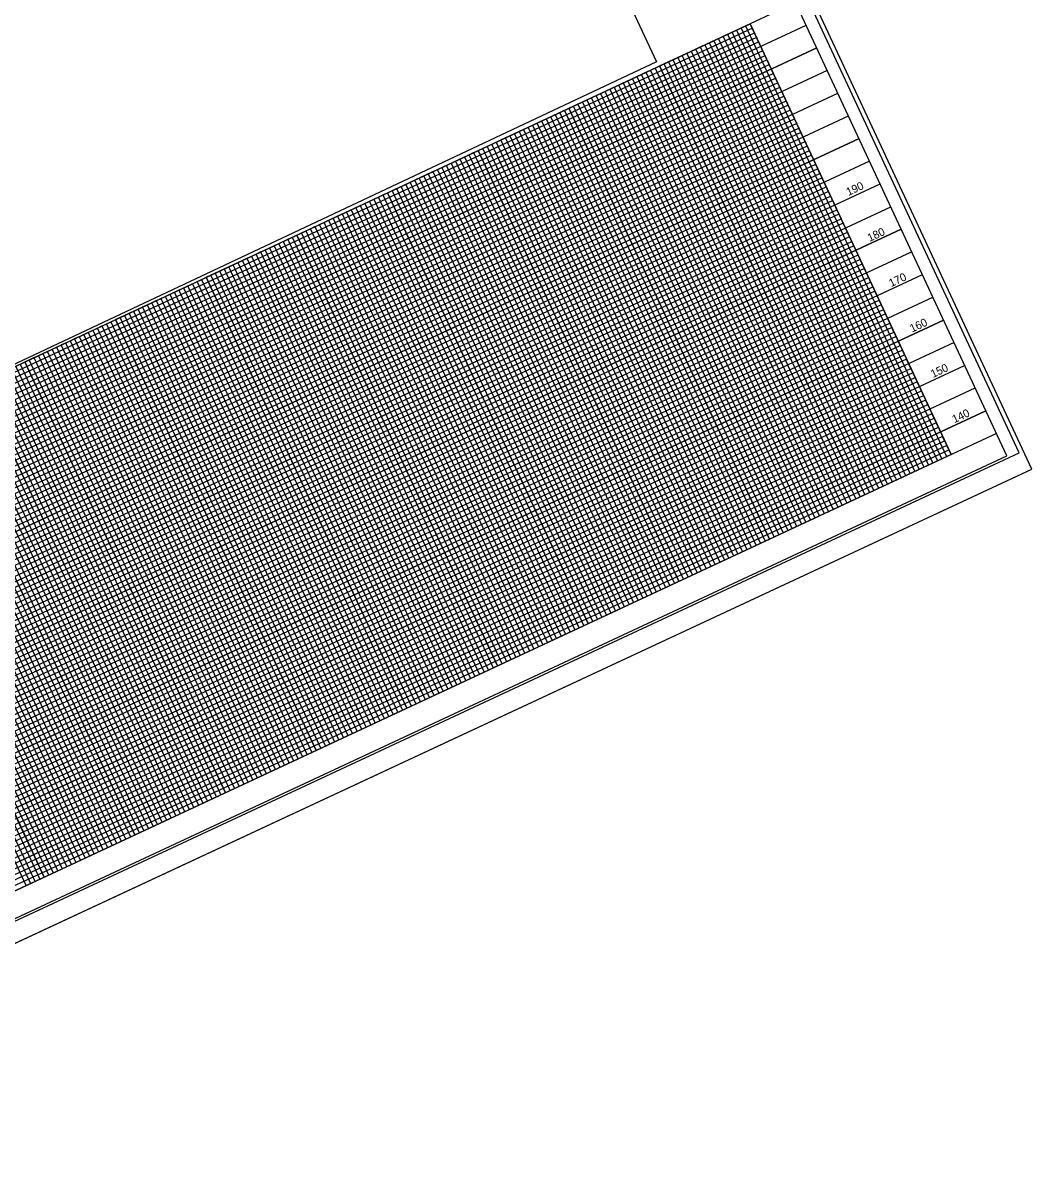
# Model space of a CAD drawing. Extents: x 2321825 to 2323872, y 921700 to 923436.
# Drawn here: x 2322864 to 2323872, y 921700 to 922857 of the extents above; entities that cross this region are included whole.
import ezdxf

# ---------------------------------------------------------------- set-up
doc = ezdxf.new("R2010")
doc.units = 0
for name, color, linetype in [('Default', 7, 'Continuous'), ('Sheet Cutting Line CELL', 7, 'Continuous'), ('Sheet DOT Grid CELL', 7, 'Continuous'), ('Sheet Layout Plan Border', 7, 'Continuous'), ('Sheet Layout Profile Border Port 2', 7, 'Continuous'), ('Sheet Plan And Profile CELL', 7, 'Continuous'), ('Sheet Plot Border Inside CELL', 7, 'Continuous'), ('Sheet Plot Border Outside CELL', 7, 'Continuous'), ('Sheet Profile Grid Major CELL', 7, 'Continuous'), ('Sheet Profile Grid Middle CELL', 7, 'Continuous'), ('Sheet Profile Grid Minor CELL', 7, 'Continuous')]:
    doc.layers.add(name, color=color, linetype=linetype)

msp = doc.modelspace()

# ---------------------------------------------------------------- linework, layer by layer
at = {"layer": 'Sheet Cutting Line CELL'}
msp.add_line((2322346.1, 921699.6), (2323872, 922410.9), dxfattribs=at)
at = {"layer": 'Sheet DOT Grid CELL'}
for p, q in [((2322276.2, 922243.5), (2323635.8, 922877.3)), ((2323590.5, 922856.1), (2323791.2, 922425.6)), ((2322297.4, 922198.2), (2323656.9, 922831.9)), ((2323545.2, 922835), (2323745.8, 922404.5)), ((2323499.8, 922813.9), (2323700.5, 922383.4)), ((2322318.5, 922152.9), (2323678, 922786.6)), ((2323454.5, 922792.8), (2323655.2, 922362.2)), ((2323409.2, 922771.6), (2323609.9, 922341.1)), ((2323363.9, 922750.5), (2323564.6, 922320)), ((2322339.6, 922107.6), (2323699.2, 922741.3)), ((2323318.6, 922729.4), (2323519.2, 922298.9)), ((2323273.3, 922708.3), (2323473.9, 922277.7)), ((2322360.7, 922062.3), (2323720.3, 922696)), ((2323227.9, 922687.2), (2323428.6, 922256.6)), ((2323182.6, 922666), (2323383.3, 922235.5)), ((2322381.9, 922017), (2323741.4, 922650.7)), ((2323137.3, 922644.9), (2323338, 922214.4)), ((2323092, 922623.8), (2323292.7, 922193.3)), ((2322403, 921971.6), (2323762.5, 922605.4)), ((2323046.7, 922602.7), (2323247.3, 922172.1)), ((2323001.3, 922581.5), (2323202, 922151)), ((2322424.1, 921926.3), (2323783.7, 922560)), ((2322956, 922560.4), (2323156.7, 922129.9)), ((2322910.7, 922539.3), (2323111.4, 922108.8)), ((2322865.4, 922518.2), (2323066.1, 922087.6)), ((2322445.2, 921881), (2323804.8, 922514.7)), ((2322820.1, 922497), (2323020.7, 922066.5)), ((2322774.7, 922475.9), (2322975.4, 922045.4)), ((2322466.4, 921835.7), (2323825.9, 922469.4)), ((2322729.4, 922454.8), (2322930.1, 922024.3)), ((2322684.1, 922433.7), (2322884.8, 922003.1))]:
    msp.add_line(p, q, dxfattribs=at)
at = {"layer": 'Sheet Layout Plan Border'}
msp.add_lwpolyline([(2323496.8, 922818), (2322321.6, 922264.7), (2322282.6, 922345.7), (2322138.6, 922653.9), (2322100.4, 922737.9), (2323278.1, 923286)], close=True, dxfattribs=at)
at = {"layer": 'Sheet Layout Profile Border Port 2'}
msp.add_lwpolyline([(2322321.6, 922264.7), (2323590.5, 922856.1), (2323791.2, 922425.6), (2322522.2, 921834.1)], close=True, dxfattribs=at)
at = {"layer": 'Sheet Plan And Profile CELL'}
msp.add_line((2323836.5, 922446.7), (2322476.9, 921813), dxfattribs=at)
msp.add_lwpolyline([(2323403.4, 923375.8), (2322043.9, 922742.1), (2322487.5, 921790.4), (2323847, 922424.1)], close=True, dxfattribs=at)
at = {"layer": 'Sheet Plot Border Inside CELL'}
msp.add_lwpolyline([(2322349.4, 921723.2), (2323859.4, 922427.1), (2323413.7, 923383.3), (2321903.7, 922679.5)], close=True, dxfattribs=at)
at = {"layer": 'Sheet Plot Border Outside CELL'}
msp.add_lwpolyline([(2322346.1, 921699.6), (2323872, 922410.9), (2323409.3, 923403.3), (2321883.5, 922692.1)], close=True, dxfattribs=at)
at = {"layer": 'Sheet Profile Grid Major CELL'}
for points in [[(2322276.2, 922243.5), (2323635.8, 922877.3)], [(2323791.2, 922425.6), (2323590.5, 922856.1)], [(2323656.9, 922831.9), (2322297.4, 922198.2), (2322318.5, 922152.9), (2323678, 922786.6)], [(2323700.5, 922383.4), (2323499.8, 922813.9), (2323545.2, 922835), (2323745.8, 922404.5)], [(2323609.9, 922341.1), (2323409.2, 922771.6), (2323454.5, 922792.8), (2323655.2, 922362.2)], [(2323519.2, 922298.9), (2323318.6, 922729.4), (2323363.9, 922750.5), (2323564.6, 922320)], [(2323699.2, 922741.3), (2322339.6, 922107.6), (2322360.7, 922062.3), (2323720.3, 922696)], [(2323428.6, 922256.6), (2323227.9, 922687.2), (2323273.3, 922708.3), (2323473.9, 922277.7)], [(2323338, 922214.4), (2323137.3, 922644.9), (2323182.6, 922666), (2323383.3, 922235.5)], [(2323741.4, 922650.7), (2322381.9, 922017), (2322403, 921971.6), (2323762.5, 922605.4)], [(2323247.3, 922172.1), (2323046.7, 922602.7), (2323092, 922623.8), (2323292.7, 922193.3)], [(2323156.7, 922129.9), (2322956, 922560.4), (2323001.3, 922581.5), (2323202, 922151)], [(2323783.7, 922560), (2322424.1, 921926.3), (2322445.2, 921881), (2323804.8, 922514.7)], [(2323066.1, 922087.6), (2322865.4, 922518.2), (2322910.7, 922539.3), (2323111.4, 922108.8)], [(2322975.4, 922045.4), (2322774.7, 922475.9), (2322820.1, 922497), (2323020.7, 922066.5)], [(2323825.9, 922469.4), (2322466.4, 921835.7)], [(2322884.8, 922003.1), (2322684.1, 922433.7), (2322729.4, 922454.8), (2322930.1, 922024.3)]]:
    msp.add_lwpolyline(points, dxfattribs=at)
at = {"layer": 'Sheet Profile Grid Middle CELL'}
for p, q in [((2322286.8, 922220.9), (2323646.4, 922854.6)), ((2323667.5, 922809.3), (2322307.9, 922175.6)), ((2322329.1, 922130.3), (2323688.6, 922764)), ((2323709.7, 922718.7), (2322350.2, 922084.9)), ((2322371.3, 922039.6), (2323730.9, 922673.3)), ((2323752, 922628), (2322392.4, 921994.3)), ((2322413.5, 921949), (2323773.1, 922582.7)), ((2323794.2, 922537.4), (2322434.7, 921903.7)), ((2322455.8, 921858.3), (2323815.4, 922492.1))]:
    msp.add_line(p, q, dxfattribs=at)
for points in [[(2323723.2, 922393.9), (2323522.5, 922824.5), (2323567.8, 922845.6), (2323768.5, 922415.1)], [(2323632.5, 922351.7), (2323431.9, 922782.2), (2323477.2, 922803.3), (2323677.9, 922372.8)], [(2323541.9, 922309.4), (2323341.2, 922740), (2323386.5, 922761.1), (2323587.2, 922330.6)], [(2323451.3, 922267.2), (2323250.6, 922697.7), (2323295.9, 922718.8), (2323496.6, 922288.3)], [(2323360.6, 922224.9), (2323160, 922655.5), (2323205.3, 922676.6), (2323406, 922246.1)], [(2323270, 922182.7), (2323069.3, 922613.2), (2323114.6, 922634.3), (2323315.3, 922203.8)], [(2323179.4, 922140.4), (2322978.7, 922571), (2323024, 922592.1), (2323224.7, 922161.6)], [(2323088.7, 922098.2), (2322888, 922528.7), (2322933.4, 922549.8), (2323134, 922119.3)], [(2322998.1, 922055.9), (2322797.4, 922486.5), (2322842.7, 922507.6), (2323043.4, 922077.1)], [(2322907.4, 922013.7), (2322706.8, 922444.2), (2322752.1, 922465.3), (2322952.8, 922034.8)]]:
    msp.add_lwpolyline(points, dxfattribs=at)
at = {"layer": 'Sheet Profile Grid Minor CELL'}
for points in [[(2323782.1, 922421.4), (2323581.4, 922851.9), (2323585.9, 922854), (2323786.6, 922423.5)], [(2322325.8, 922255.6), (2323594.7, 922847.1), (2323592.6, 922851.6), (2322323.7, 922260.1)], [(2322330, 922246.5), (2323598.9, 922838), (2323596.8, 922842.5), (2322327.9, 922251.1)], [(2323759.4, 922410.8), (2323558.8, 922841.4), (2323563.3, 922843.5), (2323764, 922412.9)], [(2323773, 922417.2), (2323572.4, 922847.7), (2323576.9, 922849.8), (2323777.6, 922419.3)], [(2323736.8, 922400.3), (2323536.1, 922830.8), (2323540.6, 922832.9), (2323741.3, 922402.4)], [(2323750.4, 922406.6), (2323549.7, 922837.1), (2323554.2, 922839.2), (2323754.9, 922408.7)], [(2322336.3, 922232.9), (2323605.3, 922824.4), (2323603.2, 922829), (2322334.2, 922237.5)], [(2322340.6, 922223.9), (2323609.5, 922815.4), (2323607.4, 922819.9), (2322338.5, 922228.4)], [(2323714.1, 922389.7), (2323513.4, 922820.2), (2323518, 922822.3), (2323718.6, 922391.8)], [(2323727.7, 922396), (2323527, 922826.6), (2323531.6, 922828.7), (2323732.2, 922398.2)], [(2323682.4, 922374.9), (2323481.7, 922805.4), (2323486.2, 922807.6), (2323686.9, 922377)], [(2323691.5, 922379.1), (2323490.8, 922809.7), (2323495.3, 922811.8), (2323696, 922381.3)], [(2323705.1, 922385.5), (2323504.4, 922816), (2323508.9, 922818.1), (2323709.6, 922387.6)], [(2322346.9, 922210.3), (2323615.8, 922801.8), (2323613.7, 922806.3), (2322344.8, 922214.8)], [(2322351.1, 922201.2), (2323620.1, 922792.7), (2323617.9, 922797.2), (2322349, 922205.8)], [(2323659.7, 922364.4), (2323459.1, 922794.9), (2323463.6, 922797), (2323664.3, 922366.5)], [(2323668.8, 922368.6), (2323468.1, 922799.1), (2323472.7, 922801.2), (2323673.3, 922370.7)], [(2323637.1, 922353.8), (2323436.4, 922784.3), (2323440.9, 922786.4), (2323641.6, 922355.9)], [(2323646.1, 922358), (2323445.5, 922788.5), (2323450, 922790.7), (2323650.7, 922360.1)], [(2322357.5, 922187.6), (2323626.4, 922779.1), (2323624.3, 922783.6), (2322355.4, 922192.2)], [(2322361.7, 922178.6), (2323630.6, 922770), (2323628.5, 922774.6), (2322359.6, 922183.1)], [(2323614.4, 922343.2), (2323413.7, 922773.8), (2323418.3, 922775.9), (2323618.9, 922345.3)], [(2323623.5, 922347.5), (2323422.8, 922778), (2323427.3, 922780.1), (2323628, 922349.6)], [(2322365.9, 922169.5), (2323634.8, 922761)], [(2323591.8, 922332.7), (2323391.1, 922763.2), (2323395.6, 922765.3), (2323596.3, 922334.8)], [(2323600.8, 922336.9), (2323400.1, 922767.4), (2323404.7, 922769.5), (2323605.4, 922339)], [(2322370.1, 922160.4), (2323639.1, 922751.9), (2323637, 922756.4), (2322368, 922165)], [(2323569.1, 922322.1), (2323368.4, 922752.6), (2323373, 922754.7), (2323573.6, 922324.2)], [(2323578.2, 922326.3), (2323377.5, 922756.9), (2323382, 922759), (2323582.7, 922328.4)], [(2322376.5, 922146.8), (2323645.4, 922738.3), (2323641.2, 922747.4), (2322372.3, 922155.9)], [(2323532.8, 922305.2), (2323332.2, 922735.7), (2323336.7, 922737.8), (2323537.4, 922307.3)], [(2323546.4, 922311.5), (2323345.8, 922742.1), (2323350.3, 922744.2), (2323551, 922313.7)], [(2323555.5, 922315.8), (2323354.8, 922746.3), (2323359.4, 922748.4), (2323560, 922317.9)], [(2322380.7, 922137.8), (2323649.6, 922729.3), (2323647.5, 922733.8), (2322378.6, 922142.3)], [(2323510.2, 922294.6), (2323309.5, 922725.2), (2323314, 922727.3), (2323514.7, 922296.8)], [(2323523.8, 922301), (2323323.1, 922731.5), (2323327.6, 922733.6), (2323528.3, 922303.1)], [(2322387, 922124.2), (2323656, 922715.7), (2323651.7, 922724.7), (2322382.8, 922133.2)], [(2323487.5, 922284.1), (2323286.8, 922714.6), (2323291.4, 922716.7), (2323492.1, 922286.2)], [(2323501.1, 922290.4), (2323300.4, 922720.9), (2323305, 922723.1), (2323505.7, 922292.5)], [(2322391.3, 922115.1), (2323660.2, 922706.6), (2323658.1, 922711.1), (2322389.2, 922119.7)], [(2323464.9, 922273.5), (2323264.2, 922704.1), (2323268.7, 922706.2), (2323469.4, 922275.6)], [(2323478.5, 922279.9), (2323277.8, 922710.4), (2323282.3, 922712.5), (2323483, 922282)], [(2322397.6, 922101.5), (2323666.5, 922693), (2323662.3, 922702.1), (2322393.4, 922110.6)], [(2323433.1, 922258.7), (2323232.5, 922689.3), (2323237, 922691.4), (2323437.7, 922260.8)], [(2323442.2, 922263), (2323241.5, 922693.5), (2323246.1, 922695.6), (2323446.7, 922265.1)], [(2323455.8, 922269.3), (2323255.1, 922699.8), (2323259.7, 922701.9), (2323460.3, 922271.4)], [(2322401.8, 922092.5), (2323670.8, 922683.9), (2323668.6, 922688.5), (2322399.7, 922097)], [(2323410.5, 922248.2), (2323209.8, 922678.7), (2323214.3, 922680.8), (2323415, 922250.3)], [(2323419.5, 922252.4), (2323218.9, 922682.9), (2323223.4, 922685), (2323424.1, 922254.5)], [(2322408.2, 922078.9), (2323677.1, 922670.3), (2323672.9, 922679.4), (2322403.9, 922087.9)], [(2323387.8, 922237.6), (2323187.1, 922668.1), (2323191.7, 922670.3), (2323392.4, 922239.7)], [(2323396.9, 922241.8), (2323196.2, 922672.4), (2323200.7, 922674.5), (2323401.4, 922244)], [(2322412.4, 922069.8), (2323681.3, 922661.3), (2323679.2, 922665.8), (2322410.3, 922074.3)], [(2322418.7, 922056.2), (2323687.7, 922647.7), (2323683.4, 922656.7), (2322414.5, 922065.3)], [(2323365.2, 922227.1), (2323164.5, 922657.6), (2323169, 922659.7), (2323369.7, 922229.2)], [(2323374.2, 922231.3), (2323173.6, 922661.8), (2323178.1, 922663.9), (2323378.8, 922233.4)], [(2323342.5, 922216.5), (2323141.8, 922647), (2323146.4, 922649.1), (2323347, 922218.6)], [(2323351.6, 922220.7), (2323150.9, 922651.2), (2323155.4, 922653.4), (2323356.1, 922222.8)], [(2322423, 922047.1), (2323691.9, 922638.6), (2323689.8, 922643.1), (2322420.8, 922051.7)], [(2322429.3, 922033.5), (2323698.2, 922625), (2323694, 922634.1), (2322425.1, 922042.6)], [(2323319.8, 922205.9), (2323119.2, 922636.5), (2323123.7, 922638.6), (2323324.4, 922208)], [(2323328.9, 922210.2), (2323128.2, 922640.7), (2323132.8, 922642.8), (2323333.4, 922212.3)], [(2323297.2, 922195.4), (2323096.5, 922625.9), (2323101, 922628), (2323301.7, 922197.5)], [(2323306.3, 922199.6), (2323105.6, 922630.1), (2323110.1, 922632.2), (2323310.8, 922201.7)], [(2322433.5, 922024.5), (2323702.4, 922616), (2323700.3, 922620.5), (2322431.4, 922029)], [(2322439.9, 922010.9), (2323708.8, 922602.4), (2323704.6, 922611.4), (2322435.6, 922020)], [(2323260.9, 922178.5), (2323060.3, 922609), (2323064.8, 922611.1), (2323265.5, 922180.6)], [(2323274.5, 922184.8), (2323073.8, 922615.3), (2323078.4, 922617.4), (2323279.1, 922186.9)], [(2323283.6, 922189), (2323082.9, 922619.6), (2323087.4, 922621.7), (2323288.1, 922191.1)], [(2323238.3, 922167.9), (2323037.6, 922598.4), (2323042.1, 922600.5), (2323242.8, 922170)], [(2323251.9, 922174.2), (2323051.2, 922604.8), (2323055.7, 922606.9), (2323256.4, 922176.4)], [(2322444.1, 922001.8), (2323713, 922593.3), (2323710.9, 922597.8), (2322442, 922006.4)], [(2322450.4, 921988.2), (2323719.3, 922579.7), (2323715.1, 922588.8), (2322446.2, 921997.3)], [(2323215.6, 922157.3), (2323014.9, 922587.9), (2323019.5, 922590), (2323220.1, 922159.5)], [(2323229.2, 922163.7), (2323028.5, 922594.2), (2323033.1, 922596.3), (2323233.7, 922165.8)], [(2323193, 922146.8), (2322992.3, 922577.3), (2322996.8, 922579.4), (2323197.5, 922148.9)], [(2323206.5, 922153.1), (2323005.9, 922583.6), (2323010.4, 922585.8), (2323211.1, 922155.2)], [(2322454.6, 921979.2), (2323723.6, 922570.6), (2323721.5, 922575.2), (2322452.5, 921983.7)], [(2322461, 921965.6), (2323729.9, 922557), (2323725.7, 922566.1), (2322456.8, 921974.6)], [(2323161.2, 922132), (2322960.6, 922562.5), (2322965.1, 922564.6), (2323165.8, 922134.1)], [(2323170.3, 922136.2), (2322969.6, 922566.7), (2322974.1, 922568.9), (2323174.8, 922138.3)], [(2323183.9, 922142.6), (2322983.2, 922573.1), (2322987.7, 922575.2), (2323188.4, 922144.7)], [(2322465.2, 921956.5), (2323734.1, 922548), (2323732, 922552.5), (2322463.1, 921961)], [(2323138.6, 922121.4), (2322937.9, 922552), (2322942.4, 922554.1), (2323143.1, 922123.5)], [(2323147.6, 922125.7), (2322947, 922556.2), (2322951.5, 922558.3), (2323152.2, 922127.8)], [(2322471.5, 921942.9), (2323740.5, 922534.4), (2323736.2, 922543.4), (2322467.3, 921952)], [(2323115.9, 922110.9), (2322915.2, 922541.4), (2322919.8, 922543.5), (2323120.4, 922113)], [(2323125, 922115.1), (2322924.3, 922545.6), (2322928.8, 922547.7), (2323129.5, 922117.2)], [(2322475.8, 921933.8), (2323744.7, 922525.3), (2323742.6, 922529.8), (2322473.7, 921938.4)], [(2323093.3, 922100.3), (2322892.6, 922530.8), (2322897.1, 922532.9), (2323097.8, 922102.4)], [(2323102.3, 922104.5), (2322901.6, 922535.1), (2322906.2, 922537.2), (2323106.8, 922106.6)], [(2322482.1, 921920.2), (2323751, 922511.7), (2323746.8, 922520.8), (2322477.9, 921929.3)], [(2323070.6, 922089.7), (2322869.9, 922520.3), (2322874.4, 922522.4), (2323075.1, 922091.9)], [(2323079.7, 922094), (2322879, 922524.5), (2322883.5, 922526.6), (2323084.2, 922096.1)], [(2322486.3, 921911.2), (2323755.2, 922502.7), (2323753.1, 922507.2), (2322484.2, 921915.7)], [(2323047.9, 922079.2), (2322847.3, 922509.7), (2322851.8, 922511.8), (2323052.5, 922081.3)], [(2323057, 922083.4), (2322856.3, 922513.9), (2322860.9, 922516), (2323061.5, 922085.5)], [(2322492.7, 921897.6), (2323761.6, 922489.1), (2323757.4, 922498.1), (2322488.4, 921906.7)], [(2323011.7, 922062.3), (2322811, 922492.8), (2322815.5, 922494.9), (2323016.2, 922064.4)], [(2323025.3, 922068.6), (2322824.6, 922499.1), (2322829.1, 922501.3), (2323029.8, 922070.7)], [(2323034.3, 922072.8), (2322833.7, 922503.4), (2322838.2, 922505.5), (2323038.9, 922075)], [(2322520.1, 921838.7), (2323789, 922430.1), (2323786.9, 922434.7), (2322518, 921843.2), (2322515.9, 921847.7), (2323784.8, 922439.2), (2323782.7, 922443.7), (2322513.8, 921852.3), (2322511.7, 921856.8), (2322509.6, 921861.3), (2323778.5, 922452.8), (2323776.4, 922457.3), (2322507.5, 921865.9), (2322505.3, 921870.4), (2323774.3, 922461.9), (2323772.1, 922466.4), (2322503.2, 921874.9), (2322501.1, 921879.5), (2322499, 921884), (2323767.9, 922475.5), (2323765.8, 922480), (2322496.9, 921888.5), (2322494.8, 921893.1), (2323763.7, 922484.5)], [(2322989, 922051.7), (2322788.3, 922482.2), (2322792.9, 922484.4), (2322993.6, 922053.8)], [(2323002.6, 922058.1), (2322801.9, 922488.6), (2322806.5, 922490.7), (2323007.1, 922060.2)], [(2322966.4, 922041.2), (2322765.7, 922471.7), (2322770.2, 922473.8), (2322970.9, 922043.3)], [(2322980, 922047.5), (2322779.3, 922478), (2322783.8, 922480.1), (2322984.5, 922049.6)], [(2322943.7, 922030.6), (2322743, 922461.1), (2322747.6, 922463.2), (2322948.2, 922032.7)], [(2322957.3, 922036.9), (2322756.6, 922467.5), (2322761.2, 922469.6), (2322961.8, 922039)], [(2322912, 922015.8), (2322711.3, 922446.3), (2322715.8, 922448.5), (2322916.5, 922017.9)], [(2322921, 922020), (2322720.4, 922450.6), (2322724.9, 922452.7), (2322925.6, 922022.1)], [(2322934.6, 922026.4), (2322734, 922456.9), (2322738.5, 922459), (2322939.2, 922028.5)], [(2322889.3, 922005.2), (2322688.6, 922435.8), (2322693.2, 922437.9), (2322893.9, 922007.4)], [(2322898.4, 922009.5), (2322697.7, 922440), (2322702.2, 922442.1), (2322902.9, 922011.6)], [(2322866.7, 921994.7), (2322666, 922425.2), (2322670.5, 922427.3), (2322871.2, 921996.8)], [(2322875.7, 921998.9), (2322675, 922429.4), (2322679.6, 922431.6), (2322880.3, 922001)]]:
    msp.add_lwpolyline(points, dxfattribs=at)

# ---------------------------------------------------------------- texts
at = {"layer": 'Default'}
for s, p in [('190', (2323688.6, 922683.9)), ('180', (2323709.8, 922638)), ('170', (2323731.3, 922592.8)), ('160', (2323752.2, 922547.4)), ('150', (2323773.1, 922502)), ('140', (2323794.5, 922456.8))]:
    msp.add_text(s, height=8, rotation=24.9913, dxfattribs=at).set_placement(p)

doc.saveas('drawing.dxf')
